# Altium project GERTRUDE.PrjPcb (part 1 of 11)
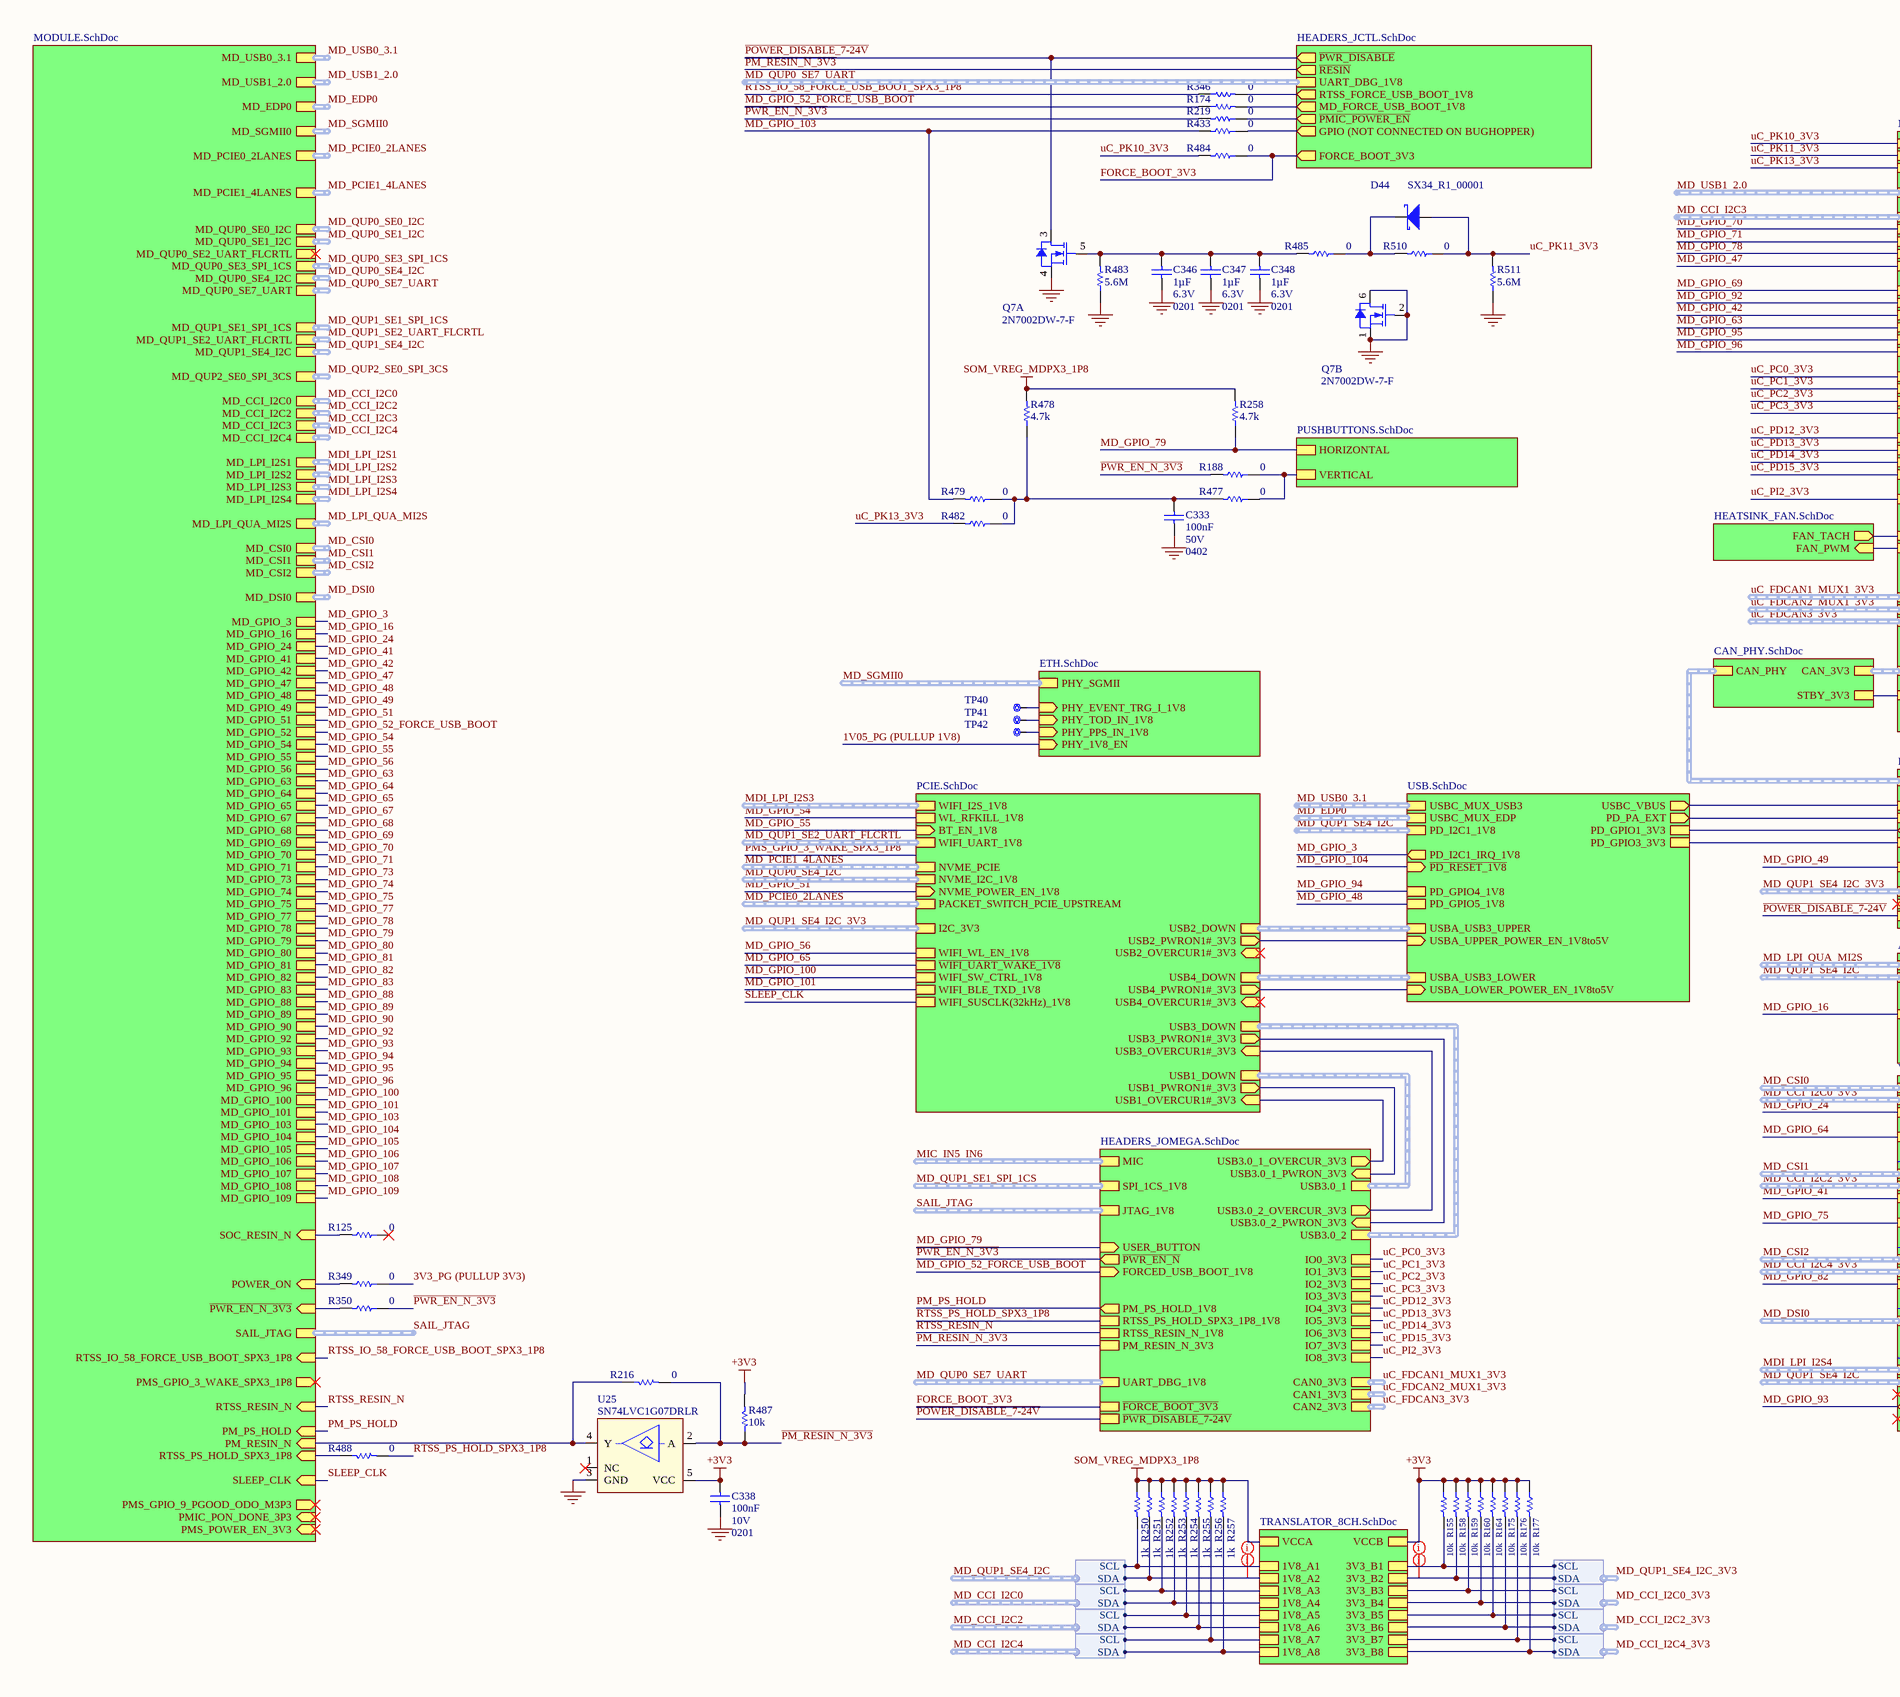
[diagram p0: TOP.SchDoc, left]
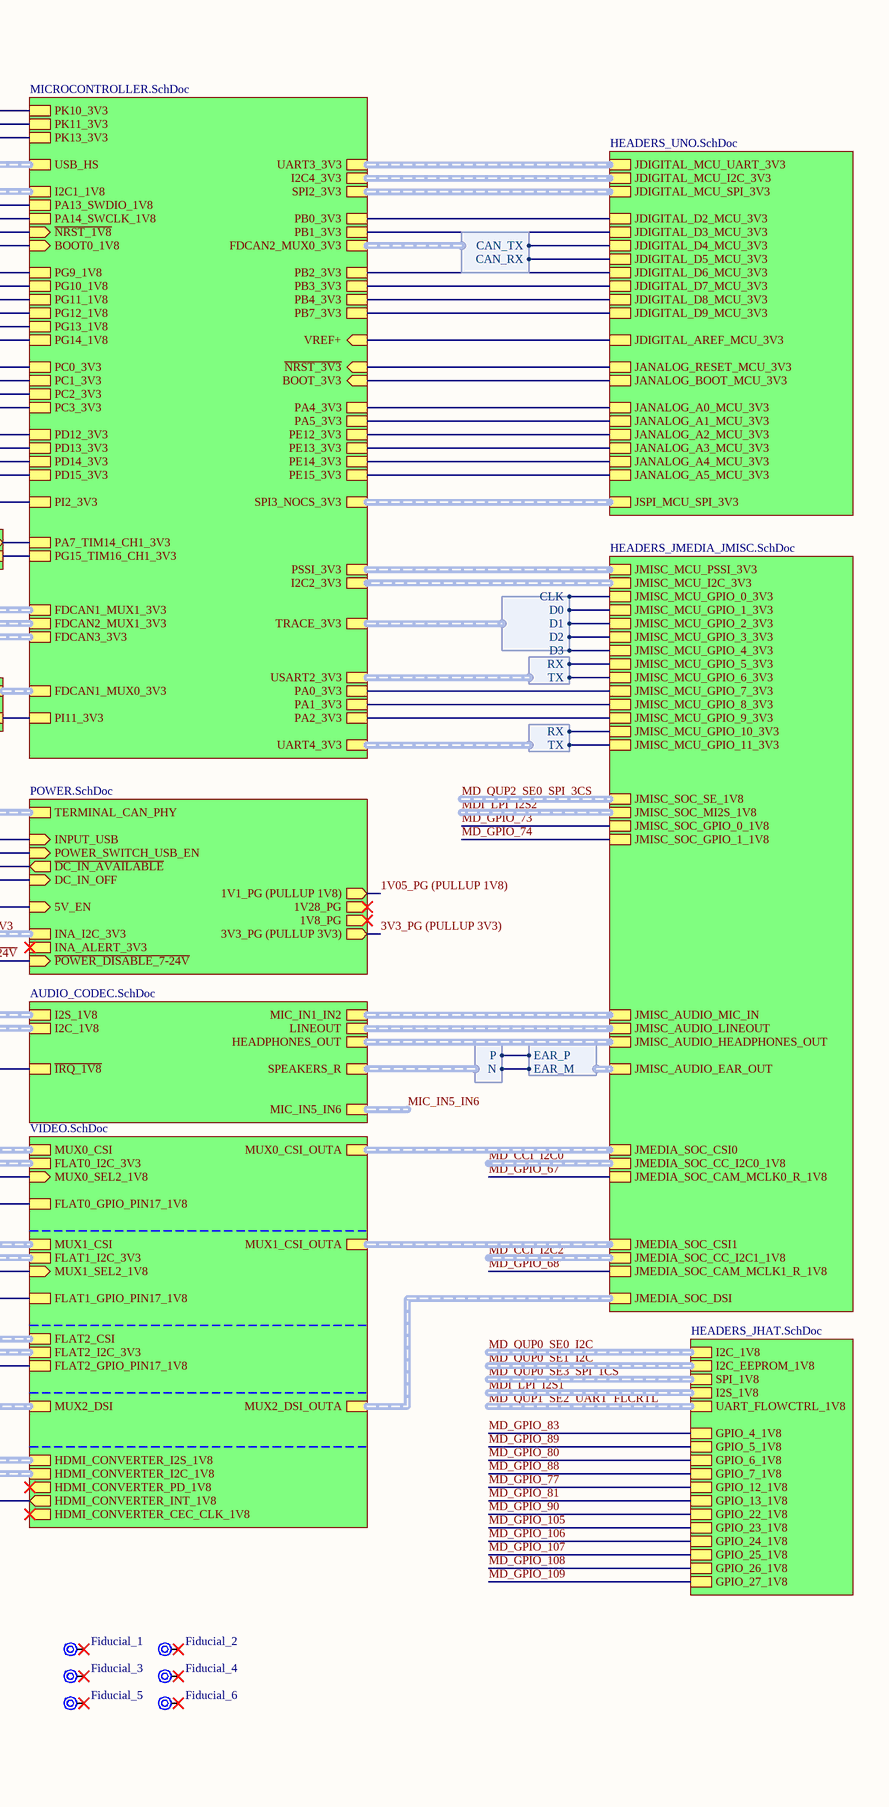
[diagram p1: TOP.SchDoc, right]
ASSEMBLY_BGA: X; ASSEMBLY_PRESSFIT: _; ASSEMBLY_SMD: X; ASSEMBLY_THT: X; BOARD_CODENAME: GERTRUDE; BOARD_INFO_AUTHOR: Silvio Navaretti; BOARD_INFO_AUTHOR_REV: Silvio Navaretti; BOARD_INFO_Er: _; BOARD_INFO_FLEX: _; BOARD_INFO_FR4: X; BOARD_INFO_FR4_HTG: _; BOARD_INFO_IPC1: _; BOARD_INFO_IPC2: X; BOARD_INFO_IPC3: _; BOARD_INFO_IPC_NA: X; BOARD_INFO_NUMBER_OF_LAYERS: 10; BOARD_INFO_PCB_SIZE: 100x160mm; BOARD_INFO_POLYMIDE: _; BOARD_INFO_RIGID: X; BOARD_INFO_RIGID/FLEX: _; BOARD_INFO_TBD: _; BOARD_INFO_THICKNESS: 2mm; DRILLS_BLIND: X; DRILLS_BURIED: X; DRILLS_COPPER_FILLING: X; DRILLS_FULL: X; DRILLS_LASER: X; DRILLS_PRESSFIT: _; DRILLS_RESIN_FILLING: _; DRILLS_SLOT: X; DRILLS_SOLDER_FILLING: _; FINISH_ADJUSTMENTS: _; FINISH_EDGE_PLATING: _; FINISH_ENIG: X; FINISH_HAL: _; FINISH_HAL_LF: _; FINISH_NI/AU: _; FINISH_SILK_BOTTOM: X; FINISH_SILK_COLOR: WHITE; FINISH_SILK_TOP: X; FINISH_SN/PB: _; FINISH_SOLDERMASK_BOTTOM: X; FINISH_SOLDERMASK_COLOR: BLUE; FINISH_SOLDERMASK_PEELABLE_BOTTOM: _; FINISH_SOLDERMASK_PEELABLE_COLOR: _; FINISH_SOLDERMASK_PEELABLE_TOP: _; FINISH_SOLDERMASK_TOP: X; FINISH_TABS: _; FINISH_TBD: _; INSULATION_MIN_INNER: 0.084mm; INSULATION_MIN_OUTER: 0.084mm; PANEL_MILLING: X; PANEL_NOT_REQUESTED: _; PANEL_NUMBER_OF_FIGURES: _; PANEL_PROVIDED: _; PANEL_REQUESTED: X; PANEL_SCORING: X; PANEL_SIZE: _; PANEL_TABS: _; SKU: ABX00163; TRACK_MIN_WIDTH_INNER: 0.084mm; TRACK_MIN_WIDTH_OUTER: 0.084mm; Version: V1.0; VIA_1: X; VIA_1_HOLE_MM: 0.1; VIA_1_PAD_MM: 0.25; VIA_2: 0.2; VIA_2_HOLE_MM: 0.4; VIA_2_PAD_MM: _; VIA_3: _; VIA_3_HOLE_MM: _; VIA_3_PAD_MM: _; VIA_4: _; VIA_4_HOLE_MM: _; VIA_4_PAD_MM: _; VIA_5: _; VIA_5_HOLE_MM: _; VIA_5_PAD_MM: _; VIA_THROUGH: X; VIA_THROUGH_HOLE_MM: 0.3; VIA_THROUGH_PAD_MM: 0.6
51 sheets, 1358 parts. Net scope: hierarchical (ports join the sheet entries above them; power ports are global).
Board file: PCB.PcbDoc
Sheets:
  TOP.SchDoc
    MODULE = MODULE.SchDoc
      MODULE_GND = MODULE_GND.SchDoc
      MODULE_PWR = MODULE_PWR.SchDoc
      MODULE_SAIL = MODULE_SAIL.SchDoc
      U_SOM_MD = MODULE_MD.SchDoc
      MODULE_SAIL_FLASH = MODULE_SAIL_FLASH.SchDoc
      MODULE_STRAPS_MD = MODULE_STRAPS_MD.SchDoc
      MODULE_STRAPS_SAIL = MODULE_STRAPS_SAIL.SchDoc
      MODULE_CONTROL = MODULE_CONTROL.SchDoc
    U_USB = USB.SchDoc
      U_USB_USBC = USB_USBC.SchDoc
      U_USB_MUX = USB_MUX.SchDoc
      U_USB_PD_CONTROLLER = USB_PD_CONTROLLER.SchDoc
        T8CH_ = TRANSLATOR_8CH.SchDoc
      U_USB_USBA = USB_USBA.SchDoc
      U_LOAD_SWITCH_5V = LOAD_SWITCH_5V.SchDoc
      U_LOAD_SWITCH_5V = LOAD_SWITCH_5V.SchDoc
    U_ETH = ETH.SchDoc
      U_ETH_PHY = ETH_PHY.SchDoc
        U_LOAD_SWITCH_5V = LOAD_SWITCH_5V.SchDoc
      U_ETH_RJ45 = ETH_RJ45.SchDoc
    U_HEADERS_UNO = HEADERS_UNO.SchDoc
    U_POWER = POWER.SchDoc
      U_POWER_SOM = POWER_DCDC_SOM.SchDoc
      U_POWER_DCDC_CARRIER = POWER_REGULATORS_CARRIER.SchDoc
      U_LOAD_SWITCH_5V = LOAD_SWITCH_5V.SchDoc
      U_LOAD_SWITCH_5V = LOAD_SWITCH_5V.SchDoc
    U_AUDIO_CODEC = AUDIO_CODEC.SchDoc
    U_HEADERS_JHAT = HEADERS_JHAT.SchDoc
      T8CH_ = TRANSLATOR_8CH.SchDoc
      T8CH_ = TRANSLATOR_8CH.SchDoc
      T8CH_ = TRANSLATOR_8CH.SchDoc
      U_TRANSLATOR_4CH = TRANSLATOR_4CH.SchDoc
    U_MIPI = VIDEO.SchDoc
      U_HDMI = HDMI.SchDoc
        U_HDMI_CONNECTOR = HDMI_CONNECTOR.SchDoc
        U_HDMI_CONVERTER = HDMI_CONVERTER.SchDoc
      U_MIPI_MUX = MIPI_MUX.SchDoc
      U_MIPI_MUX = MIPI_MUX.SchDoc
      U_MIPI_FLAT_22PIN = MIPI_FLAT_22PIN.SchDoc
      U_MIPI_FLAT_22PIN = MIPI_FLAT_22PIN.SchDoc
      U_MIPI_MUX = MIPI_MUX.SchDoc
      U_MIPI_FLAT_22PIN = MIPI_FLAT_22PIN.SchDoc
      U_TRANSLATOR_4CH = TRANSLATOR_4CH.SchDoc
    U_PUSHBUTTONS = PUSHBUTTONS.SchDoc
    U_HEADERS_JALFA_JBETA = HEADERS_JOMEGA.SchDoc
    U_MICROCONTROLLER = MICROCONTROLLER.SchDoc
      U_STM32 = STM32.SchDoc
      U_LED = LED.SchDoc
        U_LED_MATRIX = LED_MATRIX.SchDoc
        U_LED_RGB = LED_RGB.SchDoc
        U_LED_RGB = LED_RGB.SchDoc
        U_LED_RGB = LED_RGB.SchDoc
        U_LED_RGB = LED_RGB.SchDoc
      U_QWIIC = QWIIC.SchDoc
      U_ANALOG_SWITCH = ANALOG_SWITCH.SchDoc
      U_TRANSLATOR_4CH = TRANSLATOR_4CH.SchDoc
    U_HEADERS_JMEDIA_JMISC = HEADERS_JMEDIA_JMISC.SchDoc
    U_HEADERS_JCTL = HEADERS_JCTL.SchDoc
    T8CH_ = TRANSLATOR_8CH.SchDoc
    U_HEATSINK_FAN = HEATSINK_FAN.SchDoc
    U_PCIE = PCIE.SchDoc
      U_PCIE_PACKET_SWITCH = PCIE_PACKET_SWITCH.SchDoc
      U_PCIE_NVME = PCIE_NVME.SchDoc
        U_LOAD_SWITCH_5V = LOAD_SWITCH_5V.SchDoc
      U_WIFI_BLE = WIFI_BLE.SchDoc
        U_TRANSLATOR_4CH = TRANSLATOR_4CH.SchDoc
      U_PCIE_USB = PCIE_USB.SchDoc
      U_TRANSLATOR_4CH = TRANSLATOR_4CH.SchDoc
    U_CAN_PHY = CAN_PHY.SchDoc

## Sheet TOP.SchDoc: TOP
size A2; Author: Silvio Navaretti; CompanyName: ARDUINO; DrawnBy: Silvio Navaretti; Engineer: Silvio Navaretti; Organization: ARDUINO; SheetNumber: 1; SheetTotal: 51; RevAuthor: Silvio Navaretti

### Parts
C333  value 100nF  Voltage: 50V  Case Code (Imperial): 0402  [CAP-0402]  (hidden comment: GRM155R61H104KE19D)
C338  value 100nF  Voltage: 10V  Case Code (Imperial): 0201  [CAP-0201]  (hidden comment: CL03A104KP3NNNC)
C346  value 1µF  Voltage: 6.3V  Case Code (Imperial): 0201  [CAP-0201]  (hidden comment: GRM033R60J105MEA2D)
C347  value 1µF  Voltage: 6.3V  Case Code (Imperial): 0201  [CAP-0201]  (hidden comment: GRM033R60J105MEA2D)
C348  value 1µF  Voltage: 6.3V  Case Code (Imperial): 0201  [CAP-0201]  (hidden comment: GRM033R60J105MEA2D)
D44  SX34_R1_00001  [SMA DO214AC]
Fiducial_1  Fiducial mark 1mm with 2mm solder  [Fiducial mark 1mm with circle-Footprint-1]  (value not drawn)  (no BOM)
Fiducial_2  Fiducial mark 1mm with 2mm solder  [Fiducial mark 1mm with circle-Footprint-1]  (value not drawn)  (no BOM)
Fiducial_3  Fiducial mark 1mm with 2mm solder  [Fiducial mark 1mm with circle-Footprint-1]  (value not drawn)  (no BOM)
Fiducial_4  Fiducial mark 1mm with 2mm solder  [Fiducial mark 1mm with circle-Footprint-1]  (value not drawn)  (no BOM)
Fiducial_5  Fiducial mark 1mm with 2mm solder  [Fiducial mark 1mm with circle-Footprint-1]  (value not drawn)  (no BOM)
Fiducial_6  Fiducial mark 1mm with 2mm solder  [Fiducial mark 1mm with circle-Footprint-1]  (value not drawn)  (no BOM)
Q7  2N7002DW-7-F  [SOT363]  (parts A,B of 2)
R125  value 0  [RES-0201]  (hidden comment: CRCW02010000Z0ED)
R155  value 10k  [RES-0201]  (hidden comment: RC0201FR-0710KL)
R158  value 10k  [RES-0201]  (hidden comment: RC0201FR-0710KL)
R159  value 10k  [RES-0201]  (hidden comment: RC0201FR-0710KL)
R160  value 10k  [RES-0201]  (hidden comment: RC0201FR-0710KL)
R164  value 10k  [RES-0201]  (hidden comment: RC0201FR-0710KL)
R174  value 0  [RES-0201]  (hidden comment: CRCW02010000Z0ED)
R175  value 10k  [RES-0201]  (hidden comment: RC0201FR-0710KL)
R176  value 10k  [RES-0201]  (hidden comment: RC0201FR-0710KL)
R177  value 10k  [RES-0201]  (hidden comment: RC0201FR-0710KL)
R188  value 0  [RES-0201]  (hidden comment: CRCW02010000Z0ED)
R216  value 0  [RES-0201]  (hidden comment: CRCW02010000Z0ED)
R219  value 0  [RES-0201]  (hidden comment: CRCW02010000Z0ED)
R250  value 1k  [RES-0201]  (hidden comment: RC0201FR-071KL)
R251  value 1k  [RES-0201]  (hidden comment: RC0201FR-071KL)
R252  value 1k  [RES-0201]  (hidden comment: RC0201FR-071KL)
R253  value 1k  [RES-0201]  (hidden comment: RC0201FR-071KL)
R254  value 1k  [RES-0201]  (hidden comment: RC0201FR-071KL)
R255  value 1k  [RES-0201]  (hidden comment: RC0201FR-071KL)
R256  value 1k  [RES-0201]  (hidden comment: RC0201FR-071KL)
R257  value 1k  [RES-0201]  (hidden comment: RC0201FR-071KL)
R258  value 4.7k  [RES-0201]  (hidden comment: RC0201FR-074K7L)
R346  value 0  [RES-0201]  (hidden comment: CRCW02010000Z0ED)
R349  value 0  [RES-0201]  (hidden comment: CRCW02010000Z0ED)
R350  value 0  [RES-0201]  (hidden comment: CRCW02010000Z0ED)
R433  value 0  [RES-0201]  (hidden comment: CRCW02010000Z0ED)
R477  value 0  [RES-0201]  (hidden comment: CRCW02010000Z0ED)
R478  value 4.7k  [RES-0201]  (hidden comment: RC0201FR-074K7L)
R479  value 0  [RES-0201]  (hidden comment: CRCW02010000Z0ED)
R482  value 0  [RES-0201]  (hidden comment: CRCW02010000Z0ED)
R483  value 5.6M  [RES-0201]  (hidden comment: RC0201FR-075M6L)
R484  value 0  [RES-0201]  (hidden comment: CRCW02010000Z0ED)
R485  value 0  [RES-0201]  (hidden comment: CRCW02010000Z0ED)
R487  value 10k  [RES-0201]  (hidden comment: RC0201FR-0710KL)
R488  value 0  [RES-0201]  (hidden comment: CRCW02010000Z0ED)
R510  value 0  [RES-0201]  (hidden comment: CRCW02010000Z0ED)
R511  value 5.6M  [RES-0201]  (hidden comment: RC0201FR-075M6L)
TP40  Test point 1.00mm  [TP-1.00MM]  (value not drawn)  (no BOM)
TP41  Test point 1.00mm  [TP-1.00MM]  (value not drawn)  (no BOM)
TP42  Test point 1.00mm  [TP-1.00MM]  (value not drawn)  (no BOM)
U25  SN74LVC1G07DRLR  [TI DRL DRL0005A]

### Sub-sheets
MODULE = MODULE.SchDoc: MD_GPIO_3, MD_GPIO_16, MD_GPIO_24, MD_GPIO_42, MD_GPIO_47, MD_GPIO_48, MD_GPIO_54, MD_GPIO_55, MD_GPIO_63, MD_GPIO_64, MD_GPIO_65, MD_GPIO_67, MD_GPIO_68, MD_GPIO_69, MD_GPIO_70, MD_GPIO_71, MD_GPIO_73, MD_GPIO_74, MD_GPIO_75, MD_GPIO_77, MD_GPIO_78, MD_GPIO_79, MD_GPIO_80, MD_GPIO_81, MD_GPIO_83, MD_GPIO_88, MD_GPIO_89, MD_GPIO_90, MD_GPIO_92, MD_GPIO_94, MD_GPIO_95, MD_GPIO_100, MD_GPIO_101, MD_GPIO_104, MD_GPIO_105, MD_GPIO_106, MD_GPIO_107, MD_GPIO_108, MD_GPIO_109, MD_GPIO_52, MD_GPIO_56, MD_GPIO_93, MD_LPI_I2S1 (harness SOM_MD_I2S), MD_LPI_I2S4 (harness SOM_MD_I2S), MD_LPI_I2S3 (harness SOM_MD_I2S), MD_LPI_I2S2 (harness SOM_MD_I2S), MD_CSI0, MD_CSI1, MD_CSI2, MD_DSI0, MD_EDP0, MD_SGMII0, MD_USB0_3.1, MD_USB1_2.0, MD_QUP2_SE0_SPI_3CS (harness SOM_MD_SPI_3CS), MD_CCI_I2C0 (harness I2C), MD_CCI_I2C2 (harness I2C), MD_CCI_I2C3 (harness I2C), MD_CCI_I2C4 (harness I2C), MD_QUP0_SE4_I2C (harness I2C), MD_QUP0_SE3_SPI_1CS (harness SPI), MD_QUP0_SE1_I2C (harness I2C), MD_QUP0_SE7_UART (harness UART), MD_QUP0_SE0_I2C (harness I2C), MD_QUP1_SE2_UART_FLCRTL (harness SOM_MD_UART_FLCRTL), MD_QUP1_SE1_SPI_1CS (harness SPI), MD_QUP1_SE4_I2C (harness I2C), MD_GPIO_103, MD_GPIO_49, MD_GPIO_51, MD_GPIO_96, MD_GPIO_41, MD_GPIO_82, MD_PCIE1_4LANES, POWER_ON (in), MD_LPI_QUA_MI2S (harness SOM_MD_I2S_QUA), SAIL_JTAG, RTSS_IO_58_FORCE_USB_BOOT_SPX3_1P8 (in), SOC_RESIN_N (in), MD_PCIE0_2LANES, PMS_GPIO_3_WAKE_SPX3_1P8 (out), RTSS_RESIN_N (in), PM_PS_HOLD (in), PM_RESIN_N (in), RTSS_PS_HOLD_SPX3_1P8 (in), MD_QUP0_SE2_UART_FLCRTL (harness SOM_MD_UART_FLCRTL), ~{PWR_EN_N_3V3} (in), SLEEP_CLK (in), PMS_GPIO_9_PGOOD_ODO_M3P3 (out), PMIC_PON_DONE_3P3 (in), PMS_POWER_EN_3V3 (in)
T8CH_ = TRANSLATOR_8CH.SchDoc: 1V8_A1, 1V8_A2, 1V8_A3, 1V8_A4, 1V8_A5, 1V8_A6, 1V8_A7, 1V8_A8, 3V3_B1, 3V3_B2, 3V3_B3, 3V3_B4, 3V3_B5, 3V3_B6, 3V3_B7, 3V3_B8, VCCA, VCCB
U_AUDIO_CODEC = AUDIO_CODEC.SchDoc: I2C_1V8 (harness I2C), HEADPHONES_OUT (harness HEADPHONES), MIC_IN1_IN2 (harness MIC), MIC_IN5_IN6 (harness MIC), ~{IRQ_1V8}, LINEOUT (harness LINEOUT), SPEAKERS_R (harness SPEAKERS), I2S_1V8 (harness SOM_MD_I2S_QUA)
U_CAN_PHY = CAN_PHY.SchDoc: CAN_PHY (harness CAN_PHY), STBY_3V3, CAN_3V3 (harness CAN)
U_ETH = ETH.SchDoc: PHY_SGMII, PHY_EVENT_TRG_I_1V8 (in), PHY_TOD_IN_1V8 (in), PHY_PPS_IN_1V8 (in), PHY_1V8_EN (in)
U_HEADERS_JALFA_JBETA = HEADERS_JOMEGA.SchDoc: JTAG_1V8 (harness SOM_SAIL_JTAG), MIC (harness MIC), SPI_1CS_1V8 (harness SPI), USB3.0_1 (harness SOM_MD_USB0), USB3.0_1_PWRON_3V3 (in), USB3.0_1_OVERCUR_3V3 (out), USB3.0_2 (harness SOM_MD_USB0), USB3.0_2_PWRON_3V3 (in), USB3.0_2_OVERCUR_3V3 (out), CAN0_3V3 (harness CAN), CAN1_3V3 (harness CAN), CAN2_3V3 (harness CAN), USER_BUTTON (in), FORCED_USB_BOOT_1V8 (in), IO0_3V3, IO1_3V3, IO2_3V3, IO3_3V3, IO4_3V3, IO5_3V3, IO6_3V3, IO7_3V3, IO8_3V3, PM_PS_HOLD_1V8 (out), RTSS_PS_HOLD_SPX3_1P8_1V8, RTSS_RESIN_N_1V8, PM_RESIN_N_3V3, ~{PWR_EN_N} (out), UART_DBG_1V8 (harness UART), ~{FORCE_BOOT_3V3}, ~{PWR_DISABLE_7-24V}
U_HEADERS_JCTL = HEADERS_JCTL.SchDoc: UART_DBG_1V8 (harness UART), MD_FORCE_USB_BOOT_1V8 (out), RTSS_FORCE_USB_BOOT_1V8 (out), ~{PWR_DISABLE} (out), ~{PMIC_POWER_EN} (out), GPIO (NOT CONNECTED ON BUGHOPPER) (out), ~{RESIN} (out), FORCE_BOOT_3V3 (out)
U_HEADERS_JHAT = HEADERS_JHAT.SchDoc: I2C_1V8 (harness I2C), I2C_EEPROM_1V8 (harness I2C), SPI_1V8 (harness SPI), I2S_1V8 (harness SOM_MD_I2S), UART_FLOWCTRL_1V8 (harness SOM_MD_UART_FLCRTL), GPIO_4_1V8, GPIO_5_1V8, GPIO_6_1V8, GPIO_7_1V8, GPIO_13_1V8, GPIO_22_1V8, GPIO_23_1V8, GPIO_24_1V8, GPIO_25_1V8, GPIO_26_1V8, GPIO_27_1V8, GPIO_12_1V8
U_HEADERS_JMEDIA_JMISC = HEADERS_JMEDIA_JMISC.SchDoc: JMISC_MCU_PSSI_3V3 (harness PSSI), JMISC_MCU_I2C_3V3 (harness I2C), JMEDIA_SOC_CAM_MCLK0_R_1V8, JMEDIA_SOC_CAM_MCLK1_R_1V8, JMEDIA_SOC_CC_I2C1_1V8 (harness I2C), JMISC_AUDIO_EAR_OUT (harness EAT), JMISC_AUDIO_MIC_IN (harness MIC), JMISC_AUDIO_LINEOUT (harness LINEOUT), JMISC_AUDIO_HEADPHONES_OUT (harness HEADPHONES), JMISC_SOC_SE_1V8 (harness SOM_MD_SPI_3CS), JMEDIA_SOC_CSI1 (harness MIPI_4LANES), JMISC_SOC_MI2S_1V8 (harness SOM_MD_I2S), JMISC_SOC_GPIO_0_1V8, JMISC_SOC_GPIO_1_1V8, JMEDIA_SOC_DSI (harness MIPI_4LANES), JMEDIA_SOC_CSI0 (harness MIPI_4LANES), JMEDIA_SOC_CC_I2C0_1V8 (harness I2C), JMISC_MCU_GPIO_0_3V3, JMISC_MCU_GPIO_1_3V3, JMISC_MCU_GPIO_2_3V3, JMISC_MCU_GPIO_3_3V3, JMISC_MCU_GPIO_4_3V3, JMISC_MCU_GPIO_5_3V3, JMISC_MCU_GPIO_6_3V3, JMISC_MCU_GPIO_7_3V3, JMISC_MCU_GPIO_8_3V3, JMISC_MCU_GPIO_9_3V3, JMISC_MCU_GPIO_10_3V3, JMISC_MCU_GPIO_11_3V3
U_HEADERS_UNO = HEADERS_UNO.SchDoc: JDIGITAL_MCU_SPI_3V3 (harness SPI), JDIGITAL_MCU_UART_3V3 (harness UART), JDIGITAL_MCU_I2C_3V3 (harness I2C), JSPI_MCU_SPI_3V3 (harness JSPI_SPI), JDIGITAL_D2_MCU_3V3, JDIGITAL_D3_MCU_3V3, JDIGITAL_D4_MCU_3V3, JDIGITAL_D5_MCU_3V3, JDIGITAL_D6_MCU_3V3, JDIGITAL_D7_MCU_3V3, JDIGITAL_D8_MCU_3V3, JDIGITAL_D9_MCU_3V3, JANALOG_A5_MCU_3V3, JANALOG_A4_MCU_3V3, JANALOG_A3_MCU_3V3, JANALOG_A2_MCU_3V3, JANALOG_A1_MCU_3V3, JANALOG_A0_MCU_3V3, JDIGITAL_AREF_MCU_3V3, JANALOG_RESET_MCU_3V3, JANALOG_BOOT_MCU_3V3
U_HEATSINK_FAN = HEATSINK_FAN.SchDoc: FAN_TACH (out), FAN_PWM (in)
U_MICROCONTROLLER = MICROCONTROLLER.SchDoc: PG9_1V8, PG10_1V8, PG11_1V8, PG12_1V8, PG13_1V8, PG14_1V8, I2C1_1V8, ~{NRST_1V8} (in), BOOT0_1V8 (in), PA13_SWDIO_1V8, PA14_SWCLK_1V8, USB_HS, PB0_3V3, PB1_3V3, PB2_3V3, PB3_3V3, PB4_3V3, PB7_3V3, SPI2_3V3, I2C4_3V3, FDCAN2_MUX0_3V3 (harness CAN), UART3_3V3, PA4_3V3, PA5_3V3, PE12_3V3, PE13_3V3, PE14_3V3, PE15_3V3, SPI3_NOCS_3V3, BOOT_3V3 (in), ~{NRST_3V3} (in), VREF+ (in), PSSI_3V3, I2C2_3V3, PA0_3V3, PA1_3V3, PA2_3V3, PC0_3V3, PC1_3V3, PC2_3V3, PC3_3V3, PA7_TIM14_CH1_3V3, PG15_TIM16_CH1_3V3, TRACE_3V3 (harness MCU_TRACE), USART2_3V3 (harness UART), FDCAN1_MUX1_3V3, FDCAN2_MUX1_3V3, FDCAN3_3V3, PD12_3V3, PD13_3V3, PD14_3V3, PD15_3V3, PI2_3V3, PI11_3V3, UART4_3V3 (harness UART), FDCAN1_MUX0_3V3, PK13_3V3, PK10_3V3, PK11_3V3
U_MIPI = VIDEO.SchDoc: MUX0_CSI, MUX1_CSI, FLAT2_CSI, MUX2_DSI, MUX0_CSI_OUTA, MUX1_CSI_OUTA, HDMI_CONVERTER_PD_1V8 (out), HDMI_CONVERTER_INT_1V8 (out), HDMI_CONVERTER_CEC_CLK_1V8 (out), MUX2_DSI_OUTA, FLAT0_GPIO_PIN17_1V8, FLAT1_GPIO_PIN17_1V8, FLAT2_GPIO_PIN17_1V8, FLAT0_I2C_3V3, FLAT1_I2C_3V3, FLAT2_I2C_3V3, MUX0_SEL2_1V8 (in), MUX1_SEL2_1V8 (in), HDMI_CONVERTER_I2C_1V8 (harness I2C), HDMI_CONVERTER_I2S_1V8 (harness I2C)
U_PCIE = PCIE.SchDoc: USB1_DOWN, USB1_PWRON1#_3V3 (out), USB1_OVERCUR1#_3V3 (in), USB2_DOWN, USB2_PWRON1#_3V3 (out), USB2_OVERCUR1#_3V3 (in), USB3_PWRON1#_3V3 (out), USB3_OVERCUR1#_3V3 (in), WIFI_I2S_1V8, I2C_3V3, NVME_I2C_1V8, NVME_PCIE, NVME_POWER_EN_1V8 (in), WIFI_UART_1V8, USB4_DOWN, USB4_PWRON1#_3V3 (out), USB4_OVERCUR1#_3V3 (in), PACKET_SWITCH_PCIE_UPSTREAM (harness SOM_MD_PCIE0), USB3_DOWN (harness SOM_MD_USB0), WL_RFKILL_1V8, ~{WIFI_UART_WAKE_1V8}, BT_EN_1V8 (in), WIFI_SW_CTRL_1V8, WIFI_WL_EN_1V8, WIFI_BLE_TXD_1V8, WIFI_SUSCLK(32kHz)_1V8
U_POWER = POWER.SchDoc: 5V_EN (in), INPUT_USB (in), POWER_SWITCH_USB_EN (in), 1V28_PG (out), 1V8_PG (out), TERMINAL_CAN_PHY (harness CAN_PHY), 3V3_PG (PULLUP 3V3) (out), INA_I2C_3V3 (harness I2C), INA_ALERT_3V3, DC_IN_OFF (in), 1V1_PG (PULLUP 1V8) (out), ~{DC_IN_AVAILABLE} (out), ~{POWER_DISABLE_7-24V} (in)
U_PUSHBUTTONS = PUSHBUTTONS.SchDoc: VERTICAL, HORIZONTAL
U_USB = USB.SchDoc: USBC_MUX_USB3 (harness SOM_MD_USB0), USBC_MUX_EDP (harness SOM_MD_EDP0), USBA_USB3_UPPER (harness SOM_MD_EDP0), USBA_USB3_LOWER (harness SOM_MD_EDP0), USBC_VBUS (out), USBA_UPPER_POWER_EN_1V8to5V (in), USBA_LOWER_POWER_EN_1V8to5V (in), PD_I2C1_IRQ_1V8 (out), ~{PD_RESET_1V8} (in), PD_GPIO4_1V8, PD_GPIO5_1V8, PD_I2C1_1V8 (harness I2C), PD_GPIO1_3V3, PD_GPIO3_3V3, PD_PA_EXT (out)

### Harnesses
CAN: CAN_TX, CAN_RX
EAT: EAR_P, EAR_M
SPEAKERS: N, P
I2C: SDA, SCL
UART: TX, RX
MCU_TRACE: CLK, D0, D1, D2, D3

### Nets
+3V3: C338.2 R155.1 R158.1 R159.1 R160.1 R164.1 R175.1 R176.1 R177.1 R487.2 U25.5(VCC) ; sheet T8CH_/VCCB
GND: C333.2 C338.1 C346.1 C347.1 C348.1 Q7.1(S) Q7.2(G) Q7.4(S) Q7.6(D) R483.1 R511.1 U25.3(GND)
SOM_VREG_MDPX3_1P8: R250.1 R251.1 R252.1 R253.1 R254.1 R255.1 R256.1 R257.1 R258.2 R478.2 ; sheet T8CH_/VCCA
1V05_PG (PULLUP 1V8): sheet U_ETH/PHY_1V8_EN, sheet U_POWER/1V1_PG (PULLUP 1V8)
3V3_PG (PULLUP 3V3): R349.1 ; sheet U_POWER/3V3_PG (PULLUP 3V3)
BOOT0: sheet U_HEADERS_UNO/JANALOG_BOOT_MCU_3V3, sheet U_MICROCONTROLLER/BOOT_3V3
FORCE_BOOT_3V3: R484.1 ; sheet U_HEADERS_JALFA_JBETA/~{FORCE_BOOT_3V3}, sheet U_HEADERS_JCTL/FORCE_BOOT_3V3
MD_CCI_I2C0.SCL: R252.2 ; sheet T8CH_/1V8_A3, sheet MODULE/MD_CCI_I2C0.SCL
MD_CCI_I2C0.SDA: R253.2 ; sheet T8CH_/1V8_A4, sheet MODULE/MD_CCI_I2C0.SDA
MD_CCI_I2C0_3V3.SCL: R159.2 ; sheet T8CH_/3V3_B3, sheet U_MIPI/FLAT0_I2C_3V3.SCL
MD_CCI_I2C0_3V3.SDA: R160.2 ; sheet T8CH_/3V3_B4, sheet U_MIPI/FLAT0_I2C_3V3.SDA
MD_CCI_I2C2.SCL: R254.2 ; sheet T8CH_/1V8_A5, sheet MODULE/MD_CCI_I2C2.SCL
MD_CCI_I2C2.SDA: R255.2 ; sheet T8CH_/1V8_A6, sheet MODULE/MD_CCI_I2C2.SDA
MD_CCI_I2C2_3V3.SCL: R164.2 ; sheet T8CH_/3V3_B5, sheet U_MIPI/FLAT1_I2C_3V3.SCL
MD_CCI_I2C2_3V3.SDA: R175.2 ; sheet T8CH_/3V3_B6, sheet U_MIPI/FLAT1_I2C_3V3.SDA
MD_CCI_I2C4.SCL: R256.2 ; sheet T8CH_/1V8_A7, sheet MODULE/MD_CCI_I2C4.SCL
MD_CCI_I2C4.SDA: R257.2 ; sheet T8CH_/1V8_A8, sheet MODULE/MD_CCI_I2C4.SDA
MD_CCI_I2C4_3V3.SCL: R176.2 ; sheet T8CH_/3V3_B7, sheet U_MIPI/FLAT2_I2C_3V3.SCL
MD_CCI_I2C4_3V3.SDA: R177.2 ; sheet T8CH_/3V3_B8, sheet U_MIPI/FLAT2_I2C_3V3.SDA
MD_GPIO_3: sheet MODULE/MD_GPIO_3, sheet U_USB/PD_I2C1_IRQ_1V8
MD_GPIO_16: sheet MODULE/MD_GPIO_16, sheet U_AUDIO_CODEC/~{IRQ_1V8}
MD_GPIO_24: sheet MODULE/MD_GPIO_24, sheet U_MIPI/MUX0_SEL2_1V8
MD_GPIO_41: sheet MODULE/MD_GPIO_41, sheet U_MIPI/MUX1_SEL2_1V8
MD_GPIO_42: sheet MODULE/MD_GPIO_42, sheet U_MICROCONTROLLER/PG11_1V8
MD_GPIO_45: R251.2 ; sheet T8CH_/1V8_A2, sheet MODULE/MD_QUP1_SE4_I2C.SDA
MD_GPIO_46: R250.2 ; sheet T8CH_/1V8_A1, sheet MODULE/MD_QUP1_SE4_I2C.SCL
MD_GPIO_47: sheet MODULE/MD_GPIO_47, sheet U_MICROCONTROLLER/BOOT0_1V8
MD_GPIO_48: sheet MODULE/MD_GPIO_48, sheet U_USB/PD_GPIO5_1V8
MD_GPIO_49: sheet MODULE/MD_GPIO_49, sheet U_POWER/5V_EN
MD_GPIO_51: sheet MODULE/MD_GPIO_51, sheet U_PCIE/NVME_POWER_EN_1V8
MD_GPIO_52_FORCE_USB_BOOT: R174.1 ; sheet MODULE/MD_GPIO_52, sheet U_HEADERS_JALFA_JBETA/FORCED_USB_BOOT_1V8  [project net MD_GPIO_52]
MD_GPIO_54: sheet MODULE/MD_GPIO_54, sheet U_PCIE/WL_RFKILL_1V8
MD_GPIO_55: sheet MODULE/MD_GPIO_55, sheet U_PCIE/BT_EN_1V8
MD_GPIO_56: sheet MODULE/MD_GPIO_56, sheet U_PCIE/WIFI_WL_EN_1V8
MD_GPIO_63: sheet MODULE/MD_GPIO_63, sheet U_MICROCONTROLLER/PG12_1V8
MD_GPIO_64: sheet MODULE/MD_GPIO_64, sheet U_MIPI/FLAT0_GPIO_PIN17_1V8
MD_GPIO_65: sheet MODULE/MD_GPIO_65, sheet U_PCIE/~{WIFI_UART_WAKE_1V8}
MD_GPIO_67: sheet MODULE/MD_GPIO_67, sheet U_HEADERS_JMEDIA_JMISC/JMEDIA_SOC_CAM_MCLK0_R_1V8
MD_GPIO_68: sheet MODULE/MD_GPIO_68, sheet U_HEADERS_JMEDIA_JMISC/JMEDIA_SOC_CAM_MCLK1_R_1V8
MD_GPIO_69: sheet MODULE/MD_GPIO_69, sheet U_MICROCONTROLLER/PG9_1V8
MD_GPIO_70: sheet MODULE/MD_GPIO_70, sheet U_MICROCONTROLLER/PA13_SWDIO_1V8
MD_GPIO_71: sheet MODULE/MD_GPIO_71, sheet U_MICROCONTROLLER/PA14_SWCLK_1V8
MD_GPIO_73: sheet MODULE/MD_GPIO_73, sheet U_HEADERS_JMEDIA_JMISC/JMISC_SOC_GPIO_0_1V8
MD_GPIO_74: sheet MODULE/MD_GPIO_74, sheet U_HEADERS_JMEDIA_JMISC/JMISC_SOC_GPIO_1_1V8
MD_GPIO_75: sheet MODULE/MD_GPIO_75, sheet U_MIPI/FLAT1_GPIO_PIN17_1V8
MD_GPIO_77: sheet MODULE/MD_GPIO_77, sheet U_HEADERS_JHAT/GPIO_12_1V8
MD_GPIO_78: sheet MODULE/MD_GPIO_78, sheet U_MICROCONTROLLER/~{NRST_1V8}
MD_GPIO_79: R258.1 ; sheet MODULE/MD_GPIO_79, sheet U_PUSHBUTTONS/HORIZONTAL, sheet U_HEADERS_JALFA_JBETA/USER_BUTTON
MD_GPIO_80: sheet MODULE/MD_GPIO_80, sheet U_HEADERS_JHAT/GPIO_6_1V8
MD_GPIO_81: sheet MODULE/MD_GPIO_81, sheet U_HEADERS_JHAT/GPIO_13_1V8
MD_GPIO_82: sheet MODULE/MD_GPIO_82, sheet U_MIPI/FLAT2_GPIO_PIN17_1V8
MD_GPIO_83: sheet MODULE/MD_GPIO_83, sheet U_HEADERS_JHAT/GPIO_4_1V8
MD_GPIO_88: sheet MODULE/MD_GPIO_88, sheet U_HEADERS_JHAT/GPIO_7_1V8
MD_GPIO_89: sheet MODULE/MD_GPIO_89, sheet U_HEADERS_JHAT/GPIO_5_1V8
MD_GPIO_90: sheet MODULE/MD_GPIO_90, sheet U_HEADERS_JHAT/GPIO_22_1V8
MD_GPIO_92: sheet MODULE/MD_GPIO_92, sheet U_MICROCONTROLLER/PG10_1V8
MD_GPIO_93: sheet MODULE/MD_GPIO_93, sheet U_MIPI/HDMI_CONVERTER_INT_1V8
MD_GPIO_94: sheet MODULE/MD_GPIO_94, sheet U_USB/PD_GPIO4_1V8
MD_GPIO_95: sheet MODULE/MD_GPIO_95, sheet U_MICROCONTROLLER/PG13_1V8
MD_GPIO_96: sheet MODULE/MD_GPIO_96, sheet U_MICROCONTROLLER/PG14_1V8
MD_GPIO_100: sheet MODULE/MD_GPIO_100, sheet U_PCIE/WIFI_SW_CTRL_1V8
MD_GPIO_101: sheet MODULE/MD_GPIO_101, sheet U_PCIE/WIFI_BLE_TXD_1V8
MD_GPIO_103: R433.2 R479.2 ; sheet MODULE/MD_GPIO_103
MD_GPIO_104: sheet MODULE/MD_GPIO_104, sheet U_USB/~{PD_RESET_1V8}
MD_GPIO_105: sheet MODULE/MD_GPIO_105, sheet U_HEADERS_JHAT/GPIO_23_1V8
MD_GPIO_106: sheet MODULE/MD_GPIO_106, sheet U_HEADERS_JHAT/GPIO_24_1V8
MD_GPIO_107: sheet MODULE/MD_GPIO_107, sheet U_HEADERS_JHAT/GPIO_25_1V8
MD_GPIO_108: sheet MODULE/MD_GPIO_108, sheet U_HEADERS_JHAT/GPIO_26_1V8
MD_GPIO_109: sheet MODULE/MD_GPIO_109, sheet U_HEADERS_JHAT/GPIO_27_1V8
MD_QUP1_SE4_I2C_3V3.SCL: R155.2 ; sheet T8CH_/3V3_B1, sheet U_POWER/INA_I2C_3V3.SCL
MD_QUP1_SE4_I2C_3V3.SDA: R158.2 ; sheet T8CH_/3V3_B2, sheet U_POWER/INA_I2C_3V3.SDA
NRST: sheet U_HEADERS_UNO/JANALOG_RESET_MCU_3V3, sheet U_MICROCONTROLLER/~{NRST_3V3}
~{PM_RESIN_N_3V3}: R216.2 R487.1 U25.2(A) ; sheet U_HEADERS_JALFA_JBETA/PM_RESIN_N_3V3, sheet U_HEADERS_JCTL/~{RESIN}
~{POWER_DISABLE_7-24V}: Q7.3(D) ; sheet U_POWER/~{POWER_DISABLE_7-24V}, sheet U_HEADERS_JALFA_JBETA/~{PWR_DISABLE_7-24V}, sheet U_HEADERS_JCTL/~{PWR_DISABLE}
~{PWR_EN_N_3V3}: R188.2 R219.2 R350.1 ; sheet U_HEADERS_JALFA_JBETA/~{PWR_EN_N}
PA0: sheet U_MICROCONTROLLER/PA0_3V3, sheet U_HEADERS_JMEDIA_JMISC/JMISC_MCU_GPIO_7_3V3
PA1: sheet U_MICROCONTROLLER/PA1_3V3, sheet U_HEADERS_JMEDIA_JMISC/JMISC_MCU_GPIO_8_3V3
PA2: sheet U_MICROCONTROLLER/PA2_3V3, sheet U_HEADERS_JMEDIA_JMISC/JMISC_MCU_GPIO_9_3V3
PA4: sheet U_HEADERS_UNO/JANALOG_A0_MCU_3V3, sheet U_MICROCONTROLLER/PA4_3V3
PA5: sheet U_HEADERS_UNO/JANALOG_A1_MCU_3V3, sheet U_MICROCONTROLLER/PA5_3V3
PA7: sheet U_MICROCONTROLLER/PA7_TIM14_CH1_3V3, sheet U_HEATSINK_FAN/FAN_TACH
PA11: sheet U_HEADERS_JMEDIA_JMISC/JMISC_MCU_GPIO_10_3V3, sheet U_MICROCONTROLLER/UART4_3V3.RX
PA12: sheet U_HEADERS_JMEDIA_JMISC/JMISC_MCU_GPIO_11_3V3, sheet U_MICROCONTROLLER/UART4_3V3.TX
PA_VBUS: sheet U_USB/USBC_VBUS, sheet U_POWER/INPUT_USB
PB0: sheet U_HEADERS_UNO/JDIGITAL_D2_MCU_3V3, sheet U_MICROCONTROLLER/PB0_3V3
PB1: sheet U_HEADERS_UNO/JDIGITAL_D3_MCU_3V3, sheet U_MICROCONTROLLER/PB1_3V3
PB2: sheet U_HEADERS_UNO/JDIGITAL_D6_MCU_3V3, sheet U_MICROCONTROLLER/PB2_3V3
PB3: sheet U_HEADERS_UNO/JDIGITAL_D7_MCU_3V3, sheet U_MICROCONTROLLER/PB3_3V3
PB4: sheet U_HEADERS_UNO/JDIGITAL_D8_MCU_3V3, sheet U_MICROCONTROLLER/PB4_3V3
PB5: sheet U_HEADERS_UNO/JDIGITAL_D5_MCU_3V3, sheet U_MICROCONTROLLER/FDCAN2_MUX0_3V3.CAN_RX
PB6: sheet U_HEADERS_UNO/JDIGITAL_D4_MCU_3V3, sheet U_MICROCONTROLLER/FDCAN2_MUX0_3V3.CAN_TX
PB7: sheet U_HEADERS_UNO/JDIGITAL_D9_MCU_3V3, sheet U_MICROCONTROLLER/PB7_3V3
PE2: sheet U_HEADERS_JMEDIA_JMISC/JMISC_MCU_GPIO_0_3V3, sheet U_MICROCONTROLLER/TRACE_3V3.CLK
PE3: sheet U_HEADERS_JMEDIA_JMISC/JMISC_MCU_GPIO_1_3V3, sheet U_MICROCONTROLLER/TRACE_3V3.D0
PE4: sheet U_HEADERS_JMEDIA_JMISC/JMISC_MCU_GPIO_2_3V3, sheet U_MICROCONTROLLER/TRACE_3V3.D1
PE5: sheet U_HEADERS_JMEDIA_JMISC/JMISC_MCU_GPIO_3_3V3, sheet U_MICROCONTROLLER/TRACE_3V3.D2
PE6: sheet U_HEADERS_JMEDIA_JMISC/JMISC_MCU_GPIO_4_3V3, sheet U_MICROCONTROLLER/TRACE_3V3.D3
PE7: sheet U_HEADERS_JMEDIA_JMISC/JMISC_MCU_GPIO_5_3V3, sheet U_MICROCONTROLLER/USART2_3V3.RX
PE8: sheet U_HEADERS_JMEDIA_JMISC/JMISC_MCU_GPIO_6_3V3, sheet U_MICROCONTROLLER/USART2_3V3.TX
PE12: sheet U_HEADERS_UNO/JANALOG_A2_MCU_3V3, sheet U_MICROCONTROLLER/PE12_3V3
PE13: sheet U_HEADERS_UNO/JANALOG_A3_MCU_3V3, sheet U_MICROCONTROLLER/PE13_3V3
PE14: sheet U_HEADERS_UNO/JANALOG_A4_MCU_3V3, sheet U_MICROCONTROLLER/PE14_3V3
PE15: sheet U_HEADERS_UNO/JANALOG_A5_MCU_3V3, sheet U_MICROCONTROLLER/PE15_3V3
PG15: sheet U_MICROCONTROLLER/PG15_TIM16_CH1_3V3, sheet U_HEATSINK_FAN/FAN_PWM
PI11: sheet U_MICROCONTROLLER/PI11_3V3, sheet U_CAN_PHY/STBY_3V3
PM_PS_HOLD: sheet MODULE/PM_PS_HOLD, sheet U_HEADERS_JALFA_JBETA/PM_PS_HOLD_1V8
RTSS_IO_58_FORCE_USB_BOOT_SPX3_1P8: R346.1 ; sheet MODULE/RTSS_IO_58_FORCE_USB_BOOT_SPX3_1P8
RTSS_PS_HOLD_SPX3_1P8: R488.2 ; sheet U_HEADERS_JALFA_JBETA/RTSS_PS_HOLD_SPX3_1P8_1V8
RTSS_RESIN_N: sheet MODULE/RTSS_RESIN_N, sheet U_HEADERS_JALFA_JBETA/RTSS_RESIN_N_1V8
SLEEP_CLK: sheet MODULE/SLEEP_CLK, sheet U_PCIE/WIFI_SUSCLK(32kHz)_1V8
uC_PC0_3V3: sheet U_HEADERS_JALFA_JBETA/IO0_3V3, sheet U_MICROCONTROLLER/PC0_3V3  [project net PC0]
uC_PC1_3V3: sheet U_HEADERS_JALFA_JBETA/IO1_3V3, sheet U_MICROCONTROLLER/PC1_3V3  [project net PC1]
uC_PC2_3V3: sheet U_HEADERS_JALFA_JBETA/IO2_3V3, sheet U_MICROCONTROLLER/PC2_3V3  [project net PC2]
uC_PC3_3V3: sheet U_HEADERS_JALFA_JBETA/IO3_3V3, sheet U_MICROCONTROLLER/PC3_3V3  [project net PC3]
uC_PD12_3V3: sheet U_HEADERS_JALFA_JBETA/IO4_3V3, sheet U_MICROCONTROLLER/PD12_3V3  [project net PD12]
uC_PD13_3V3: sheet U_HEADERS_JALFA_JBETA/IO5_3V3, sheet U_MICROCONTROLLER/PD13_3V3  [project net PD13]
uC_PD14_3V3: sheet U_HEADERS_JALFA_JBETA/IO6_3V3, sheet U_MICROCONTROLLER/PD14_3V3  [project net PD14]
uC_PD15_3V3: sheet U_HEADERS_JALFA_JBETA/IO7_3V3, sheet U_MICROCONTROLLER/PD15_3V3  [project net PD15]
uC_PI2_3V3: sheet U_HEADERS_JALFA_JBETA/IO8_3V3, sheet U_MICROCONTROLLER/PI2_3V3  [project net PI2]
uC_PK10_3V3: R484.2 ; sheet U_MICROCONTROLLER/PK10_3V3  [project net PK10]
uC_PK11_3V3: D44.A R510.1 R511.2 ; sheet U_MICROCONTROLLER/PK11_3V3  [project net PK11]
uC_PK13_3V3: R482.2 ; sheet U_MICROCONTROLLER/PK13_3V3  [project net PK13]
NetC107_2: sheet U_HEADERS_UNO/JDIGITAL_AREF_MCU_3V3, sheet U_MICROCONTROLLER/VREF+
NetC333_1: C333.1 R477.2 R478.1 R479.1 R482.1
NetC346_2: C346.2 C347.2 C348.2 Q7.5(G) R483.2 R485.2
NetD44_C: D44.C R485.1 R510.2
NetD61_2: R219.1 ; sheet U_HEADERS_JCTL/~{PMIC_POWER_EN}
NetD62_2: R433.1 ; sheet U_HEADERS_JCTL/GPIO (NOT CONNECTED ON BUGHOPPER)
NetD103_1: sheet U_HEADERS_JMEDIA_JMISC/JMISC_AUDIO_EAR_OUT.EAR_P, sheet U_AUDIO_CODEC/SPEAKERS_R.P
NetD103_2: sheet U_HEADERS_JMEDIA_JMISC/JMISC_AUDIO_EAR_OUT.EAR_M, sheet U_AUDIO_CODEC/SPEAKERS_R.N
NetJOMEGA_54: sheet U_HEADERS_JALFA_JBETA/USB3.0_1_PWRON_3V3, sheet U_PCIE/USB1_PWRON1#_3V3
NetJOMEGA_56: sheet U_HEADERS_JALFA_JBETA/USB3.0_1_OVERCUR_3V3, sheet U_PCIE/USB1_OVERCUR1#_3V3
NetJOMEGA_58: sheet U_HEADERS_JALFA_JBETA/USB3.0_2_PWRON_3V3, sheet U_PCIE/USB3_PWRON1#_3V3
NetJOMEGA_60: sheet U_HEADERS_JALFA_JBETA/USB3.0_2_OVERCUR_3V3, sheet U_PCIE/USB3_OVERCUR1#_3V3
NetMODULE1_A6: R216.1 U25.4(Y) ; sheet MODULE/PM_RESIN_N
NetMODULE1_BB43: R488.1 ; sheet MODULE/RTSS_PS_HOLD_SPX3_1P8
NetMODULE1_D28: R125.2 ; sheet MODULE/SOC_RESIN_N
NetPB1_3: R188.1 R477.1 ; sheet U_PUSHBUTTONS/VERTICAL
NetQ3_2: sheet U_USB/PD_GPIO3_3V3, sheet U_POWER/DC_IN_OFF
NetQ3_3: sheet U_USB/PD_GPIO1_3V3, sheet U_POWER/~{DC_IN_AVAILABLE}
NetQ4_3: R174.2 ; sheet U_HEADERS_JCTL/MD_FORCE_USB_BOOT_1V8
NetQ4_6: R346.2 ; sheet U_HEADERS_JCTL/RTSS_FORCE_USB_BOOT_1V8
NetR154_2: sheet U_USB/USBA_LOWER_POWER_EN_1V8to5V, sheet U_PCIE/USB4_PWRON1#_3V3
NetR182_2: sheet U_USB/USBA_UPPER_POWER_EN_1V8to5V, sheet U_PCIE/USB2_PWRON1#_3V3
NetR215_1: sheet U_USB/PD_PA_EXT, sheet U_POWER/POWER_SWITCH_USB_EN
NetR349_2: R349.2 ; sheet MODULE/POWER_ON
NetR350_2: R350.2 ; sheet MODULE/~{PWR_EN_N_3V3}
NetTP40_X: TP40.X ; sheet U_ETH/PHY_EVENT_TRG_I_1V8
NetTP41_X: TP41.X ; sheet U_ETH/PHY_TOD_IN_1V8
NetTP42_X: TP42.X ; sheet U_ETH/PHY_PPS_IN_1V8

Not connected (* = marked no-connect by the designer): Fiducial_1 1*; Fiducial_2 1*; Fiducial_3 1*; Fiducial_4 1*; Fiducial_5 1*; Fiducial_6 1*; R125 1*; U25 1(NC)*

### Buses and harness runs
harness MD_CCI_I2C0 = sheet MODULE/MD_CCI_I2C0
harness MD_CCI_I2C0 = sheet U_HEADERS_JMEDIA_JMISC/JMEDIA_SOC_CC_I2C0_1V8
harness MD_CCI_I2C0_3V3 = sheet U_MIPI/FLAT0_I2C_3V3
harness MD_CCI_I2C2 = sheet MODULE/MD_CCI_I2C2
harness MD_CCI_I2C2 = sheet U_HEADERS_JMEDIA_JMISC/JMEDIA_SOC_CC_I2C1_1V8
harness MD_CCI_I2C2_3V3 = sheet U_MIPI/FLAT1_I2C_3V3
harness MD_CCI_I2C3 = sheet MODULE/MD_CCI_I2C3
harness MD_CCI_I2C3 = sheet U_MICROCONTROLLER/I2C1_1V8
harness MD_CCI_I2C4 = sheet MODULE/MD_CCI_I2C4
harness MD_CCI_I2C4_3V3 = sheet U_MIPI/FLAT2_I2C_3V3
harness MD_CSI0 = sheet MODULE/MD_CSI0
harness MD_CSI0 = sheet U_MIPI/MUX0_CSI
harness MD_CSI1 = sheet MODULE/MD_CSI1
harness MD_CSI1 = sheet U_MIPI/MUX1_CSI
harness MD_CSI2 = sheet MODULE/MD_CSI2
harness MD_CSI2 = sheet U_MIPI/FLAT2_CSI
harness MD_DSI0 = sheet MODULE/MD_DSI0
harness MD_DSI0 = sheet U_MIPI/MUX2_DSI
harness MD_EDP0 = sheet MODULE/MD_EDP0
harness MD_EDP0 = sheet U_USB/USBC_MUX_EDP
harness MD_LPI_QUA_MI2S = sheet MODULE/MD_LPI_QUA_MI2S
harness MD_LPI_QUA_MI2S = sheet U_AUDIO_CODEC/I2S_1V8
harness MD_PCIE0_2LANES = sheet MODULE/MD_PCIE0_2LANES
harness MD_PCIE0_2LANES = sheet U_PCIE/PACKET_SWITCH_PCIE_UPSTREAM
harness MD_PCIE1_4LANES = sheet MODULE/MD_PCIE1_4LANES
harness MD_PCIE1_4LANES = sheet U_PCIE/NVME_PCIE
harness MD_QUP0_SE0_I2C = sheet MODULE/MD_QUP0_SE0_I2C
harness MD_QUP0_SE0_I2C = sheet U_HEADERS_JHAT/I2C_1V8
harness MD_QUP0_SE1_I2C = sheet MODULE/MD_QUP0_SE1_I2C
harness MD_QUP0_SE1_I2C = sheet U_HEADERS_JHAT/I2C_EEPROM_1V8
harness MD_QUP0_SE3_SPI_1CS = sheet MODULE/MD_QUP0_SE3_SPI_1CS
harness MD_QUP0_SE3_SPI_1CS = sheet U_HEADERS_JHAT/SPI_1V8
harness MD_QUP0_SE4_I2C = sheet MODULE/MD_QUP0_SE4_I2C
harness MD_QUP0_SE4_I2C = sheet U_PCIE/NVME_I2C_1V8
harness MD_QUP0_SE7_UART = sheet MODULE/MD_QUP0_SE7_UART
harness MD_QUP0_SE7_UART = sheet U_HEADERS_JALFA_JBETA/UART_DBG_1V8
harness MD_QUP0_SE7_UART = sheet U_HEADERS_JCTL/UART_DBG_1V8
harness MD_QUP1_SE1_SPI_1CS = sheet MODULE/MD_QUP1_SE1_SPI_1CS
harness MD_QUP1_SE1_SPI_1CS = sheet U_HEADERS_JALFA_JBETA/SPI_1CS_1V8
harness MD_QUP1_SE2_UART_FLCRTL = sheet MODULE/MD_QUP1_SE2_UART_FLCRTL
harness MD_QUP1_SE2_UART_FLCRTL = sheet U_HEADERS_JHAT/UART_FLOWCTRL_1V8
harness MD_QUP1_SE2_UART_FLCRTL = sheet U_PCIE/WIFI_UART_1V8
harness MD_QUP1_SE4_I2C = sheet MODULE/MD_QUP1_SE4_I2C
harness MD_QUP1_SE4_I2C = sheet U_AUDIO_CODEC/I2C_1V8
harness MD_QUP1_SE4_I2C = sheet U_MIPI/HDMI_CONVERTER_I2C_1V8
harness MD_QUP1_SE4_I2C = sheet U_USB/PD_I2C1_1V8
harness MD_QUP1_SE4_I2C_3V3 = sheet U_PCIE/I2C_3V3
harness MD_QUP1_SE4_I2C_3V3 = sheet U_POWER/INA_I2C_3V3
harness MD_QUP2_SE0_SPI_3CS = sheet MODULE/MD_QUP2_SE0_SPI_3CS
harness MD_QUP2_SE0_SPI_3CS = sheet U_HEADERS_JMEDIA_JMISC/JMISC_SOC_SE_1V8
harness MD_SGMII0 = sheet MODULE/MD_SGMII0
harness MD_SGMII0 = sheet U_ETH/PHY_SGMII
harness MD_USB0_3.1 = sheet MODULE/MD_USB0_3.1
harness MD_USB0_3.1 = sheet U_USB/USBC_MUX_USB3
harness MD_USB1_2.0 = sheet MODULE/MD_USB1_2.0
harness MD_USB1_2.0 = sheet U_MICROCONTROLLER/USB_HS
harness MDI_LPI_I2S1 = sheet MODULE/MD_LPI_I2S1
harness MDI_LPI_I2S1 = sheet U_HEADERS_JHAT/I2S_1V8
harness MDI_LPI_I2S2 = sheet MODULE/MD_LPI_I2S2
harness MDI_LPI_I2S2 = sheet U_HEADERS_JMEDIA_JMISC/JMISC_SOC_MI2S_1V8
harness MDI_LPI_I2S3 = sheet MODULE/MD_LPI_I2S3
harness MDI_LPI_I2S3 = sheet U_PCIE/WIFI_I2S_1V8
harness MDI_LPI_I2S4 = sheet MODULE/MD_LPI_I2S4
harness MDI_LPI_I2S4 = sheet U_MIPI/HDMI_CONVERTER_I2S_1V8
harness MIC_IN5_IN6 = sheet U_AUDIO_CODEC/MIC_IN5_IN6
harness MIC_IN5_IN6 = sheet U_HEADERS_JALFA_JBETA/MIC
harness SAIL_JTAG = sheet MODULE/SAIL_JTAG
harness SAIL_JTAG = sheet U_HEADERS_JALFA_JBETA/JTAG_1V8
harness sheet U_AUDIO_CODEC/HEADPHONES_OUT = sheet U_HEADERS_JMEDIA_JMISC/JMISC_AUDIO_HEADPHONES_OUT
harness sheet U_AUDIO_CODEC/LINEOUT = sheet U_HEADERS_JMEDIA_JMISC/JMISC_AUDIO_LINEOUT
harness sheet U_AUDIO_CODEC/MIC_IN1_IN2 = sheet U_HEADERS_JMEDIA_JMISC/JMISC_AUDIO_MIC_IN
harness sheet U_CAN_PHY/CAN_3V3 = sheet U_MICROCONTROLLER/FDCAN1_MUX0_3V3
harness sheet U_CAN_PHY/CAN_PHY = sheet U_POWER/TERMINAL_CAN_PHY
harness sheet U_HEADERS_JALFA_JBETA/USB3.0_1 = sheet U_PCIE/USB1_DOWN
harness sheet U_HEADERS_JALFA_JBETA/USB3.0_2 = sheet U_PCIE/USB3_DOWN
harness sheet U_HEADERS_JMEDIA_JMISC/JMEDIA_SOC_CSI0 = sheet U_MIPI/MUX0_CSI_OUTA
harness sheet U_HEADERS_JMEDIA_JMISC/JMEDIA_SOC_CSI1 = sheet U_MIPI/MUX1_CSI_OUTA
harness sheet U_HEADERS_JMEDIA_JMISC/JMEDIA_SOC_DSI = sheet U_MIPI/MUX2_DSI_OUTA
harness sheet U_HEADERS_JMEDIA_JMISC/JMISC_MCU_I2C_3V3 = sheet U_MICROCONTROLLER/I2C2_3V3
harness sheet U_HEADERS_JMEDIA_JMISC/JMISC_MCU_PSSI_3V3 = sheet U_MICROCONTROLLER/PSSI_3V3
harness sheet U_HEADERS_UNO/JDIGITAL_MCU_I2C_3V3 = sheet U_MICROCONTROLLER/I2C4_3V3
harness sheet U_HEADERS_UNO/JDIGITAL_MCU_SPI_3V3 = sheet U_MICROCONTROLLER/SPI2_3V3
harness sheet U_HEADERS_UNO/JDIGITAL_MCU_UART_3V3 = sheet U_MICROCONTROLLER/UART3_3V3
harness sheet U_HEADERS_UNO/JSPI_MCU_SPI_3V3 = sheet U_MICROCONTROLLER/SPI3_NOCS_3V3
harness sheet U_PCIE/USB2_DOWN = sheet U_USB/USBA_USB3_UPPER
harness sheet U_PCIE/USB4_DOWN = sheet U_USB/USBA_USB3_LOWER
harness uC_FDCAN1_MUX1_3V3 = sheet U_HEADERS_JALFA_JBETA/CAN0_3V3
harness uC_FDCAN1_MUX1_3V3 = sheet U_MICROCONTROLLER/FDCAN1_MUX1_3V3
harness uC_FDCAN2_MUX1_3V3 = sheet U_HEADERS_JALFA_JBETA/CAN1_3V3
harness uC_FDCAN2_MUX1_3V3 = sheet U_MICROCONTROLLER/FDCAN2_MUX1_3V3
harness uC_FDCAN3_3V3 = sheet U_HEADERS_JALFA_JBETA/CAN2_3V3
harness uC_FDCAN3_3V3 = sheet U_MICROCONTROLLER/FDCAN3_3V3

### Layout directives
net class NET_I2C_SYSTEM_1V8: MD_GPIO_45, MD_GPIO_46
net class NET_I2C_SYSTEM_3V3: MD_QUP1_SE4_I2C_3V3.SCL, MD_QUP1_SE4_I2C_3V3.SDA

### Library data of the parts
C333 = C0015-A.14: CAP CHIP 0402 100nF 10% 50V X5R; Manufacturer: Murata; Code Arduino: A5141
C338 = C0113-A.6: CAP CHIP 0201 100nF 10% 10V X5R; Manufacturer: Samsung Electro-Mechanics; Code Arduino: C0113
C346-C348 = C0002-A.15: CAP CHIP 0201 1uF 20% 6.3V X5R; Manufacturer: Murata; Code Arduino: A5520
D44 = D0109-A.2: DIODE SCHOTTKY SMD 3A 40V SMA DO214AC; Manufacturer: Panjit; Part Number: SX34-AU_R1_000A1; Code Arduino: D0109; Forward Voltage: 0.39V
Fiducial_1-Fiducial_6 = UT0024-A.6
Q7 = T0011-A.12: MOSFET 2N-CH 60V 0.32A SOT363; Manufacturer: Diodes Inc.; Device Type: Mosfet 2N-CH SMD; Code Arduino: A5500
R125 R174 R188 R216 R219 R346 R349 R350 R433 R477 R479 R482 R484 R485 R488 R510 = R0140-A.21: RES CHIP 0201 0R; Manufacturer: Vishay; Temperature coefficient: 0ppm; Code Arduino: R0140; Power: 50mW; Tolerance: 0%
R155 R158-R160 R164 R175-R177 R487 = R0145-A.21: RES CHIP 0201 10k 1% 1/20W; Manufacturer: Yageo; Power: 50mW; Temperature coefficient: 200ppm; Code Arduino: R0145
R250-R257 = R0195-A.22: RES CHIP 0201 1k 1% 1/20W; Manufacturer: Yageo; Power: 50mW; Temperature coefficient: 200ppm; Code Arduino: R0195
R258 R478 = R0151-A.21: RES CHIP 0201 4k7 1% 1/20W; Manufacturer: Yageo; Power: 50mW; Temperature coefficient: 200ppm; Code Arduino: A5521
R483 = R0423-A.1: RES CHIP 0201 5.6M 1% 1/20W 200ppm; Manufacturer: YAGEO; Power: 50mW; Code Arduino: R0423
R511 = R0423-A.1: RES CHIP 0201 5.6M 1% 1/20W 200ppm; Manufacturer: YAGEO; Code Arduino: R0423; Power: 50mW
TP40-TP42 = UT0013-A.6: Part Number: This is not a component
U25 = U0494-A.2: IC buffer open drain, 1.65V to 5.5V, 32mA sink current, SOT-5X3 1.6mmx1.6mm; Manufacturer: Texas Instruments; Code Arduino: U0494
